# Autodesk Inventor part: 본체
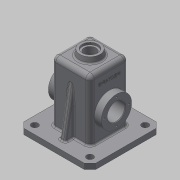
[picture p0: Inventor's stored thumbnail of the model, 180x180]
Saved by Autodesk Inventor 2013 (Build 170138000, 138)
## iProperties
Created: 2016-02
Part Number: 본체
Material: 일반
Document SubType Name: Modeling
Designer: dgall
Density: 1 g/cm^3
Author: dgall
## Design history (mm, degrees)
sketch "스케치1"
  geometry: L1 (-35, 35)-(35, 35); L2 (35, 35)-(35, -35); L3 (35, -35)-(-35, -35); L4 (-35, -35)-(-35, 35); 1 further point
  constraints: 8 end point, 2 parallel, 1 horizontal, 1 perpendicular
  dimensions: "d0" = 70 distance between parallel lines of L2 L4; "d2" = 70 distance between parallel lines of L3 L1; "d3" = 35 distance from line of point (0, 0) L1; "d4" = 35 distance from line of L4 point (0, 0)
extrude "돌출1" new body sketch "스케치1" stored distance "d5" = 120; taper "d6" = 0 deg
feature "쉘1" dims "d7" = 5
sketch "스케치2"
  geometry: L1 (35, 35)-(-35, 35) reference; L2 (-35, 35)-(-35, -35) reference; L3 (-35, -35)-(35, -35) reference; L4 (35, -35)-(35, 35) reference; L5 (-65, 65)-(65, 65); L6 (65, 65)-(65, -65); L7 (65, -65)-(-65, -65); L8 (-65, -65)-(-65, 65); 1 further point
  constraints: 8 end point, 2 parallel, 1 horizontal, 1 perpendicular
  dimensions: "d8" = 130 distance of L5.end L6.end; "d10" = 130 distance of L5.start L5.end; "d11" = 65 distance from line of point (0, 0) L5 (= 0.5 x d8); "d12" = 65 distance from line of point (0, 0) L8 (= 0.5 x d10)
extrude "돌출2" join sketch "스케치2" distance "d13" = 10; taper "d14" = 0 deg
chamfer "모따기1" distance "d15" = 10; stored, may be unused: second distance "d16" = 2, angle "d17" = 45 deg
node "작업 평면1"
sketch "스케치3"
  geometry: L1 (-55, -60)-(55, -60) reference; C1 r 27.5 at (0, -5); 1 further point
  constraints: 1 centre point
  dimensions: "d19" = 55 distance from line of L1 C1.centre; "d20" = 0 horizontal distance of point (0, 0) C1.centre; "d21" = 55 diameter of C1
extrude "돌출3" join sketch "스케치3" stored distance "d22" = 10; taper "d23" = 0 deg
sketch "스케치4"
  geometry: L1 (-30, 55)-(-30, -60) reference; L2 (-30, 22.5)-(-23, 15.5); L3 (-23, 15.5)-(-23, 11); L4 (-23, 11)-(-30, 11); L5 (-48, -32.5)-(-48, 22.5) reference; L6 (-48, -5)-(88.253, -5); L7 (-30, 22.5)-(-30, 11); 1 further point
  constraints: 10 end point, 2 perpendicular, 2 point on line, 1 collinear, 1 midpoint, 1 parallel
  dimensions: "d24" = 32 diameter of L4 L6; "d26" = 55 diameter of L2.start L6; "d27" = 7 distance between parallel lines of L1 L3; "d28" = 135 deg angle of L1 L2
revolve "회전1" sketch "스케치4" stored, may be unused: angle "d29" = 90 deg
sketch "스케치5"
  geometry: C1 r 27.5 at (0, 0) reference; C2 r 16 at (0, 0); 1 further point
  constraints: 1 centre point, 1 coincident
  dimensions: "d30" = 32 diameter of C2
extrude "돌출4" cut sketch "스케치5" stored distance "d32" = 10; taper "d33" = 0 deg
sketch "스케치7"
  geometry: C1 r 20 at (0, 0); 1 further point
  constraints: 1 centre point, 1 coincident
  dimensions: "d34" = 40 diameter of C1
extrude "돌출5" join sketch "스케치7" distance "d36" = 10; taper "d37" = -10 deg
sketch "스케치8"
  geometry: C1 r 18.237 at (0, 0) reference; C2 r 14 at (0, 0)
  constraints: 1 centre point, 1 coincident
  dimensions: "d38" = 28 diameter of C2
extrude "돌출6" cut sketch "스케치8" distance "d40" = 4; taper "d41" = 0 deg
sketch "스케치9"
  geometry: C1 r 14 at (0, 0) reference; C2 r 10.5 at (0, 0)
  constraints: 1 centre point, 1 coincident
  dimensions: "d42" = 21 diameter of C2
extrude "돌출7" cut sketch "스케치9" stored distance "d44" = 4; taper "d45" = 0 deg
fillet "모깎기1" dims "d46" = 3
fillet "모깎기2" dims "d47" = 3
fillet "모깎기3" dims "d48" = 8
fillet "모깎기4" dims "d49" = 8
chamfer "모따기2" distance "d50" = 1; stored, may be unused: second distance "d51" = 2, angle "d52" = 45 deg
fillet "모깎기5" dims "d53" = 0.5
fillet "모깎기6" dims "d54" = 0.5
sketch "스케치10"
  geometry: L1 (35, -50)-(35, 52) reference; L2 (-55, -50)-(55, -50) reference; L3 (65, -50)-(55, -50) reference; L4 (35, 35.069)-(50, -50); L5 (65, -60)-(65, -50) reference; L6 (35, 35.069)-(35, -50); L7 (35, -50)-(50, -50); 1 further point
  constraints: 6 end point, 2 collinear, 2 point on line
  dimensions: "d55" = 15 distance from line of L5 L4.end; "d57" = 10 deg angle of L4 L5
fillet "모깎기7" dims "d58" = 3
sketch "스케치11"
  geometry: L1 (55, 65)-(-55, 65) reference; L2 (-65, 55)-(-65, -55) reference; C1 r 6 at (-50, 50); 1 further point
  constraints: 1 centre point
  dimensions: "d59" = 15 distance from line of C1.centre L2; "d60" = 15 distance from line of C1.centre L1; "d61" = 12 diameter of C1
extrude "돌출8" cut sketch "스케치11" stored distance "d62" = 4; taper "d63" = 0 deg
fillet "모깎기8" dims "d70" = 0.5
extrude "돌출9" join sketch "스케치10" stored distance "d71" = 10; taper "d72" = 0 deg
fillet "모깎기9" dims "d73" = 3
fillet "모깎기10" dims "d74" = 3
fillet "모깎기11" dims "d75" = 3
fillet "모깎기12" dims "d76" = 3
fillet "모깎기13" dims "d77" = 3
sketch "스케치12"
  geometry: C1 r 17 at (0, 0) reference; A1 r 22.5 centre (0, 0) between (0, 22.5) and (22.5, 0); 3 further points
  constraints: 4 point on circle, 1 centre point, 1 coincident
  dimensions: "d78" = 45 diameter of A1
hole "구멍1" sketch "스케치12" at (0, 22.5), (22.5, 0), (0, -22.5), (-22.5, 0) diameter "d80" = 3.242; stored, may be unused: countersink angle "d84" = 90 deg, drill point angle "d86" = 118 deg; dims "d81" = 8, "d82" = 4, "d83" = 2, "d85" = 10
sketch "스케치13"
  geometry: L1 (6.261, -8.998)-(47.739, -8.998); L2 (47.739, -8.998)-(47.739, -15.002); L3 (47.739, -15.002)-(6.261, -15.002); L4 (6.261, -15.002)-(6.261, -8.998); L5 (6.261, -12)-(47.739, -12); L6 (27, -8.998)-(27, -15.002); L7 (62, -99)-(62, 0) reference; L8 (8.763, 18)-(45.237, 18) reference; 1 further point
  constraints: 4 end point, 4 midpoint, 2 other
  dimensions: "d87" = 35 distance between parallel lines of L7 L6; "d88" = 30 distance between parallel lines of L8 L5
extrude "돌출10" join sketch "스케치13" distance "d89" = 0.5; taper "d90" = 0 deg
node "솔리드1"
mirror "대칭1"
mirror "대칭2"
pattern_linear "직사각형 패턴1" dims "d66" = 100
mirror "대칭3"
mirror "대칭4"
node "작업 평면2"
other parameters: "d18" = -48
